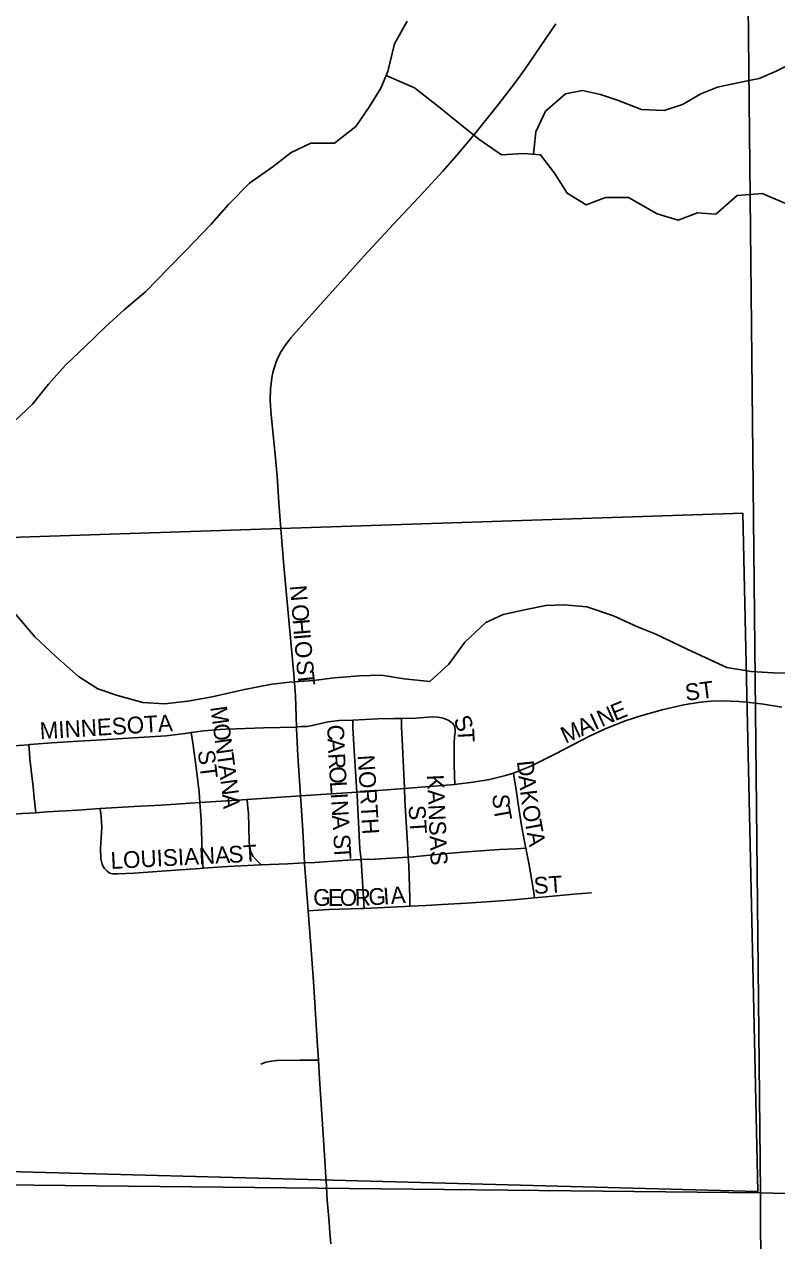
# Model space of a CAD drawing. Extents: x 1874609 to 2204689, y 815661 to 1281160.
# Drawn here: x 2005395 to 2007640, y 1009164 to 1012793 of the extents above; entities that cross this region are included whole.
import ezdxf

# ---------------------------------------------------------------- set-up
doc = ezdxf.new("R2010")
doc.units = 0
for name, color, linetype in [('GM_X_City_Street', 7, 'Continuous'), ('GM_X_City_Street_Text', 7, 'Continuous'), ('GM_X_Corporation', 7, 'Continuous'), ('GM_X_County_Road', 7, 'Continuous'), ('GM_X_Minor_River', 7, 'Continuous'), ('GM_X_Section', 7, 'Continuous'), ('GM_X_State_Route', 7, 'Continuous'), ('GM_X_Township_Road', 7, 'Continuous')]:
    doc.layers.add(name, color=color, linetype=linetype)

msp = doc.modelspace()

# ---------------------------------------------------------------- linework, layer by layer
at = {"layer": 'GM_X_City_Street'}
for points in [[(2006207.6, 1010697), (2006204, 1010789.6), (2006199.6, 1010854.4), (2006190.1, 1010951.4), (2006175.4, 1011113), (2006169.7, 1011177.7), (2006161, 1011288.6)], [(2006854.4, 1010559.4), (2006861.5, 1010561.6), (2006906.5, 1010580.3), (2006979.7, 1010616.7), (2007081.9, 1010669.4), (2007126.5, 1010690.4), (2007187.7, 1010714.8), (2007234.6, 1010730.6), (2007298.1, 1010748.4), (2007362.5, 1010762.9), (2007411.4, 1010770.8), (2007444.3, 1010774), (2007477.3, 1010775), (2007526.7, 1010773.2), (2007551.4, 1010771.4)], [(2006207.6, 1010697), (2006222.1, 1010698.2), (2006238.4, 1010698.2), (2006254.4, 1010701.2), (2006301.8, 1010712.4), (2006334.6, 1010715.8), (2006375, 1010717.7)], [(2006375, 1010717.7), (2006449.1, 1010721.3), (2006498.3, 1010721.9), (2006520.2, 1010722.5)], [(2006387.3, 1010502.9), (2006380.3, 1010610.7), (2006377.3, 1010660.4), (2006375.8, 1010696.9), (2006375, 1010717.7)], [(2006520.2, 1010722.5), (2006563.8, 1010723.5), (2006612.8, 1010727.2), (2006629.2, 1010726.5), (2006645.1, 1010723.2), (2006660, 1010717.2), (2006672.8, 1010708), (2006679.4, 1010697.9), (2006680.3, 1010683.3), (2006679.2, 1010666.8), (2006677.9, 1010650.6), (2006677.5, 1010634.3), (2006677.4, 1010601.7), (2006677.8, 1010585.4), (2006679, 1010552.7), (2006680, 1010525.5)], [(2006529.5, 1010513.4), (2006529, 1010535.8), (2006521.7, 1010679), (2006521.1, 1010695.6), (2006520.2, 1010722.5)], [(2005408.9, 1010644), (2005412, 1010644.2), (2005477.3, 1010649.2), (2005555.5, 1010654.2), (2005611, 1010657.7), (2005737.1, 1010665.7), (2005818.4, 1010671), (2005850.8, 1010674.5), (2005883.2, 1010678.7), (2005893.5, 1010680.2)], [(2005893.5, 1010680.2), (2005931.4, 1010685.8), (2005979.7, 1010689.8), (2005995.5, 1010690), (2006027.6, 1010691.7), (2006108.6, 1010693.9), (2006157.2, 1010695.4), (2006205.9, 1010696.8), (2006207.6, 1010697)], [(2005918.9, 1010471.1), (2005916.7, 1010502.3), (2005908.6, 1010567.7), (2005897.7, 1010649.4), (2005893.5, 1010680.2)], [(2006219.2, 1010491), (2006211, 1010611), (2006207.8, 1010692.2), (2006207.6, 1010697)], [(2005331.4, 1010638.6), (2005346.7, 1010639.7), (2005408.9, 1010644)], [(2005430.1, 1010441.1), (2005426.9, 1010467.8), (2005424.9, 1010484.5), (2005421.3, 1010518.1), (2005415.5, 1010568.5), (2005412, 1010602.2), (2005410.8, 1010619), (2005408.9, 1010644)], [(2006680, 1010525.5), (2006686.1, 1010526), (2006734.8, 1010531.8), (2006783, 1010540.4), (2006830.6, 1010551.8), (2006854.4, 1010559.4)], [(2006891.7, 1010335), (2006890.9, 1010339.1), (2006878.5, 1010403.2), (2006868.7, 1010467.7), (2006861.6, 1010516.4), (2006858.9, 1010532.6), (2006854.4, 1010559.4)], [(2006529.5, 1010513.4), (2006680, 1010525.5)], [(2006219.2, 1010491), (2006387.3, 1010502.9)], [(2006387.3, 1010502.9), (2006489.9, 1010510.2), (2006529.5, 1010513.4)], [(2006399.9, 1010301.1), (2006396.6, 1010332.2), (2006387.9, 1010492.5), (2006387.3, 1010502.9)], [(2006540.7, 1010308.7), (2006538.1, 1010349.6), (2006530.5, 1010478.2), (2006529.5, 1010513.4)], [(2005650.3, 1010261), (2005642.1, 1010266.4), (2005634.4, 1010274.3), (2005630.8, 1010280.6), (2005627.1, 1010288), (2005623.9, 1010303.2), (2005622.9, 1010334.5), (2005626.3, 1010397.7), (2005626, 1010413.2), (2005624.4, 1010428.5), (2005621.9, 1010453.5)], [(2005928.7, 1010275.2), (2005927.9, 1010289.7), (2005926, 1010322), (2005924.5, 1010354.5), (2005924.1, 1010387.2), (2005922.6, 1010420.1), (2005918.9, 1010471.1)], [(2006101.7, 1010285.5), (2006089.3, 1010298.5), (2006078, 1010310.3), (2006071, 1010324.8), (2006067.4, 1010340.6), (2006065.7, 1010356.8), (2006064.3, 1010439.3), (2006062.6, 1010455.1), (2006059.9, 1010480.4)], [(2006399.9, 1010301.1), (2006441.9, 1010302.8), (2006523.3, 1010307.2), (2006540.7, 1010308.7)], [(2006540.7, 1010308.7), (2006555.2, 1010309.9), (2006635.4, 1010317.3), (2006715.8, 1010323.9), (2006812.8, 1010331), (2006862, 1010333.5), (2006891.7, 1010335)], [(2006545.6, 1010161.8), (2006545.2, 1010186.1), (2006544.8, 1010218.6), (2006542.3, 1010283.8), (2006540.7, 1010308.7)], [(2006917.9, 1010187), (2006914.1, 1010209.8), (2006900.4, 1010290.8), (2006891.7, 1010335)], [(2005650.3, 1010261), (2005658.3, 1010258.9), (2005666, 1010258.5), (2005673.4, 1010258.3), (2005722.6, 1010260.9), (2005804.6, 1010266.6), (2005919.4, 1010274.6), (2005928.7, 1010275.2)], [(2005928.7, 1010275.2), (2006001.1, 1010280.2), (2006082.5, 1010284.9), (2006101.7, 1010285.5)], [(2006101.7, 1010285.5), (2006180.2, 1010288.3), (2006231.6, 1010291.1)], [(2006231.6, 1010291.1), (2006261.6, 1010292.7), (2006359.8, 1010299.5), (2006399.9, 1010301.1)], [(2006409, 1010155.6), (2006408.2, 1010169.8), (2006401.7, 1010284.1), (2006399.9, 1010301.1)], [(2006917.9, 1010187), (2007004.3, 1010195.2), (2007046, 1010198.6), (2007059.1, 1010199.7), (2007087.8, 1010202.1)], [(2006409, 1010155.6), (2006530.3, 1010161), (2006545.6, 1010161.8)], [(2006545.6, 1010161.8), (2006594.3, 1010164.6), (2006641.5, 1010166.8), (2006714.7, 1010171.6), (2006772.9, 1010175.4), (2006843.8, 1010180.1), (2006917.9, 1010187)], [(2006242.3, 1010148.8), (2006271.9, 1010150.3), (2006304.1, 1010152.1), (2006400.8, 1010155.3), (2006409, 1010155.6)], [(2006100.8, 1009690.4), (2006116.3, 1009696.8), (2006132.5, 1009700.3), (2006149.2, 1009701.8), (2006216.9, 1009702.3), (2006272.9, 1009702.7)]]:
    msp.add_lwpolyline(points, dxfattribs=at)
at = {"layer": 'GM_X_Corporation'}
msp.add_lwpolyline([(2007538.7, 1011334.5), (2007583.3, 1009310.6), (2004861.1, 1009383.2), (2004872.1, 1011246.2)], close=True, dxfattribs=at)
at = {"layer": 'GM_X_County_Road'}
msp.add_lwpolyline([(2007551.4, 1010771.4), (2007600.2, 1010765.2), (2007655.1, 1010755.7)], dxfattribs=at)
at = {"layer": 'GM_X_Minor_River'}
for points in [[(2005365.2, 1011608.4), (2005419.5, 1011660.3), (2005467.8, 1011720.2), (2005518.1, 1011776.2), (2005576.4, 1011832.1), (2005638.8, 1011892), (2005693.1, 1011941.9), (2005757.4, 1011995.8), (2005823.8, 1012063.8), (2005876.1, 1012117.7), (2005952.6, 1012197.6), (2006004.9, 1012255.5), (2006067.3, 1012319.5), (2006137.6, 1012369.3), (2006191.9, 1012411.2), (2006250.1, 1012439), (2006320.3, 1012438.7), (2006384.6, 1012488.6), (2006424.9, 1012548.6), (2006459.2, 1012602.6), (2006479.4, 1012652.7), (2006499.7, 1012734.8), (2006538, 1012802.9)], [(2006914.3, 1012405.7), (2006921.7, 1012472.2), (2006950, 1012534.2), (2007010.3, 1012586.1), (2007060.5, 1012595.9), (2007114.6, 1012583.7), (2007164.6, 1012567.4), (2007236.7, 1012539), (2007304.8, 1012536.7), (2007359, 1012554.5), (2007413.3, 1012586.3), (2007463.4, 1012606.2), (2007537.7, 1012621.9), (2007587.8, 1012631.7), (2007638, 1012653.5), (2007694.2, 1012681.4)], [(2006474.8, 1012641.2), (2006559.4, 1012604.2), (2006637.3, 1012543.6), (2006695.3, 1012495.2), (2006751.3, 1012450.8), (2006819.3, 1012404.4), (2006885.4, 1012408.1), (2006935.5, 1012403.9), (2006977.4, 1012349.5), (2007015.3, 1012289.2), (2007071.3, 1012254.8), (2007129.5, 1012276.6), (2007197.7, 1012276.3), (2007283.7, 1012227.8), (2007345.8, 1012209.5), (2007404, 1012231.3), (2007458.1, 1012227), (2007522.4, 1012282.9), (2007596.6, 1012288.6), (2007664.7, 1012260.2)], [(2005365.2, 1011038.6), (2005427.1, 1010966.1), (2005489, 1010907.7), (2005556.9, 1010847.2), (2005614.9, 1010810.8), (2005673, 1010790.5), (2005749.1, 1010770.1), (2005813.2, 1010765.8), (2005883.4, 1010773.5), (2005955.6, 1010787.2), (2006051.9, 1010808.9), (2006134.1, 1010824.5), (2006186.3, 1010830.3), (2006258.5, 1010836), (2006320.6, 1010843.8), (2006394.8, 1010849.5), (2006461, 1010851.2), (2006529.1, 1010840.8), (2006605.2, 1010832.5), (2006661.5, 1010884.4), (2006709.9, 1010950.4), (2006772.2, 1011008.3), (2006824.4, 1011032.1), (2006892.6, 1011047.9), (2006950.8, 1011059.7), (2007004.9, 1011061.4), (2007073.1, 1011055.1), (2007153.2, 1011028.7), (2007225.2, 1010996.2), (2007279.2, 1010973.9), (2007373.3, 1010929.4), (2007441.3, 1010897), (2007491.4, 1010874.7), (2007563.5, 1010862.3), (2007629.6, 1010858), (2007753.9, 1010857.5)]]:
    msp.add_lwpolyline(points, dxfattribs=at)
at = {"layer": 'GM_X_Section'}
for points in [[(2002062, 1014826.6), (2003151.7, 1014819.4), (2003151.7, 1014756.7), (2007536.1, 1014673.9), (2007591.4, 1009307.4), (2003159.1, 1009354.1), (2003159.1, 1009404.8), (2002171.6, 1009416.2)], [(2007536.1, 1014673.9), (2012928.9, 1014555.2), (2012933.5, 1014271.1), (2012954.3, 1009164.7), (2007591.4, 1009307.4)], [(2007591.4, 1009307.4), (2007610.6, 1003961), (2003166.4, 1004035.7), (2003166.3, 1004082.4), (2002275.1, 1004079.8), (2002171.6, 1009416.2), (2003159.1, 1009404.8), (2003159.1, 1009354.1)], [(2012954.3, 1009164.7), (2012952.5, 1009034.6), (2012981.3, 1003882.2), (2008513, 1003978.9), (2007610.6, 1003961), (2007591.4, 1009307.4)]]:
    msp.add_lwpolyline(points, close=True, dxfattribs=at)
at = {"layer": 'GM_X_State_Route'}
for points in [[(2006219.2, 1010491), (2006160.6, 1010487.2), (2006059.9, 1010480.4), (2006030.7, 1010478.5), (2005918.9, 1010471.1), (2005803.8, 1010463.6), (2005723, 1010460), (2005655.9, 1010455.7), (2005621.9, 1010453.5), (2005554.1, 1010449.1), (2005519.4, 1010446.9), (2005498.5, 1010445.5), (2005463.8, 1010443.3), (2005430.1, 1010441.1), (2005413.2, 1010440), (2005388.3, 1010438.4), (2005349.1, 1010435.9), (2005291, 1010432.2), (2005216.3, 1010428.1), (2005144.5, 1010424.1), (2005063.1, 1010421.9), (2005014.5, 1010423.5), (2004933.6, 1010430.3), (2004871.3, 1010436.2)], [(2006295.9, 1009344.1), (2006295.2, 1009354.8), (2006293.1, 1009386.6), (2006290, 1009435.2), (2006276.5, 1009646.7), (2006272.9, 1009702.7), (2006269.1, 1009760.4), (2006258, 1009937.2), (2006250.9, 1010031.5), (2006242.3, 1010148.8), (2006236.7, 1010224.9), (2006231.7, 1010288.7), (2006231.6, 1010291.1), (2006227, 1010369.9), (2006224.7, 1010418.9), (2006219.2, 1010491)], [(2006310.1, 1009155.2), (2006307.3, 1009187.4), (2006304.4, 1009219.8), (2006298.5, 1009284.9), (2006295.9, 1009344.1)]]:
    msp.add_lwpolyline(points, dxfattribs=at)
at = {"layer": 'GM_X_Township_Road'}
msp.add_lwpolyline([(2006161, 1011288.6), (2006155.1, 1011366), (2006151.6, 1011414.6), (2006149.7, 1011445.7), (2006143.8, 1011509.2), (2006130.6, 1011639.2), (2006128.9, 1011672.1), (2006129.4, 1011705.3), (2006133.4, 1011738.4), (2006136.8, 1011754.7), (2006141.3, 1011770.9), (2006146.9, 1011786.7), (2006153.7, 1011802), (2006161.5, 1011816.8), (2006170.3, 1011831), (2006190.3, 1011857.6), (2006244.8, 1011919.3), (2006409.2, 1012102.3), (2006509.7, 1012210.6), (2006588.1, 1012294.6), (2006643.6, 1012354.9), (2006687, 1012403.9), (2006739.6, 1012466.6), (2006811.5, 1012556.2), (2006861.2, 1012621.1), (2006889.3, 1012661.1), (2006981.6, 1012795.1)], dxfattribs=at)

# ---------------------------------------------------------------- texts
at = {"layer": 'GM_X_City_Street_Text'}
for s, rotation, p in [('N', 274.8145, (2006187.4, 1011118.1)), ('O', 274.8145, (2006192.2, 1011061.1)), ('H', 274.8141, (2006195.8, 1011017.3)), ('I', 274.8319, (2006199.5, 1010973.4)), ('O', 274.8254, (2006201.4, 1010951.5)), ('S', 274.8192, (2006206.2, 1010894.5)), ('T', 276.5093, (2006209.3, 1010857.8)), ('ST', 7.1259, (2007369.5, 1010774.7)), ('E', 22.3036, (2007157.6, 1010713.8)), ('M', 277.9382, (2005949.8, 1010756.1)), ('N', 24.5706, (2007118, 1010695.7)), ('MINNESOTA', 3.4881, (2005442.8, 1010660.4)), ('O', 277.9413, (2005957.1, 1010703.8)), ('S', 292.7754, (2006674.6, 1010719.1)), ('M', 24.5894, (2007010, 1010646.3)), ('A', 24.5706, (2007058, 1010668.3)), ('I', 24.5807, (2007098, 1010686.6)), ('C', 270.8015, (2006299.4, 1010703.6)), ('T', 272.9388, (2006687.2, 1010691)), ('N', 277.9413, (2005963.2, 1010660.2)), ('A', 272.6532, (2006300, 1010662.2)), ('ST', 277.1217, (2005912.7, 1010625.5)), ('T', 277.9501, (2005969.3, 1010616.7)), ('R', 273.295, (2006302, 1010617.6)), ('NORTH', 273.5755, (2006389.7, 1010612.2)), ('D', 275.9564, (2006864.9, 1010594.7)), ('A', 277.9384, (2005974.1, 1010581.8)), ('O', 273.5684, (2006304.3, 1010577.9)), ('N', 277.903, (2005980.2, 1010538.2)), ('L', 273.5801, (2006307.1, 1010533.9)), ('KANSAS', 272.4921, (2006596.6, 1010553.9)), ('A', 275.9542, (2006869.5, 1010551)), ('A', 273.5872, (2005986.2, 1010495.6)), ('I', 273.5792, (2006309.3, 1010498.8)), ('S', 272.5145, (2006792.2, 1010496.4)), ('K', 276.9668, (2006874.2, 1010506.3)), ('N', 273.5807, (2006310.6, 1010476.8)), ('ST', 273.5746, (2006541.5, 1010462.2)), ('T', 280.2417, (2006794.5, 1010453.9)), ('O', 280.125, (2006880, 1010459.6)), ('A', 273.5745, (2006313.4, 1010432.9)), ('T', 280.6247, (2006887.8, 1010415.8)), ('A', 280.6262, (2006894.3, 1010381.2)), ('LOUISIANA', 2.9701, (2005654, 1010273.2)), ('ST', 3.5882, (2006005.8, 1010290.8)), ('S', 273.5815, (2006317, 1010375.8)), ('T', 273.5862, (2006319.2, 1010340.7)), ('ST', 3.5878, (2006916.6, 1010198.4)), ('G', 0.0437, (2006257.2, 1010163.2)), ('E', 0.0273, (2006301.2, 1010163.2)), ('O', 0.0324, (2006336.4, 1010163.2)), ('R', 1.3416, (2006381.6, 1010163.3)), ('G', 3.812, (2006423.6, 1010164.3)), ('I', 4.0947, (2006467.7, 1010167.2)), ('A', 4.0911, (2006489.7, 1010168.8))]:
    msp.add_text(s, height=50, rotation=rotation, dxfattribs=at).set_placement(p)

doc.saveas('drawing.dxf')
